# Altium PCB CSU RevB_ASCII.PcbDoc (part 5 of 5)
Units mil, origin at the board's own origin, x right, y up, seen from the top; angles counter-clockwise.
Board outline 5905.51 x 4330.71 mil, 8 copper layers (Top Layer, InternalPlane1, MidLayer1, InternalPlane2, MidLayer2, InternalPlane3, MidLayer3, Bottom Layer); 265 components, 387 nets, 1910 pads, 1151 vias.
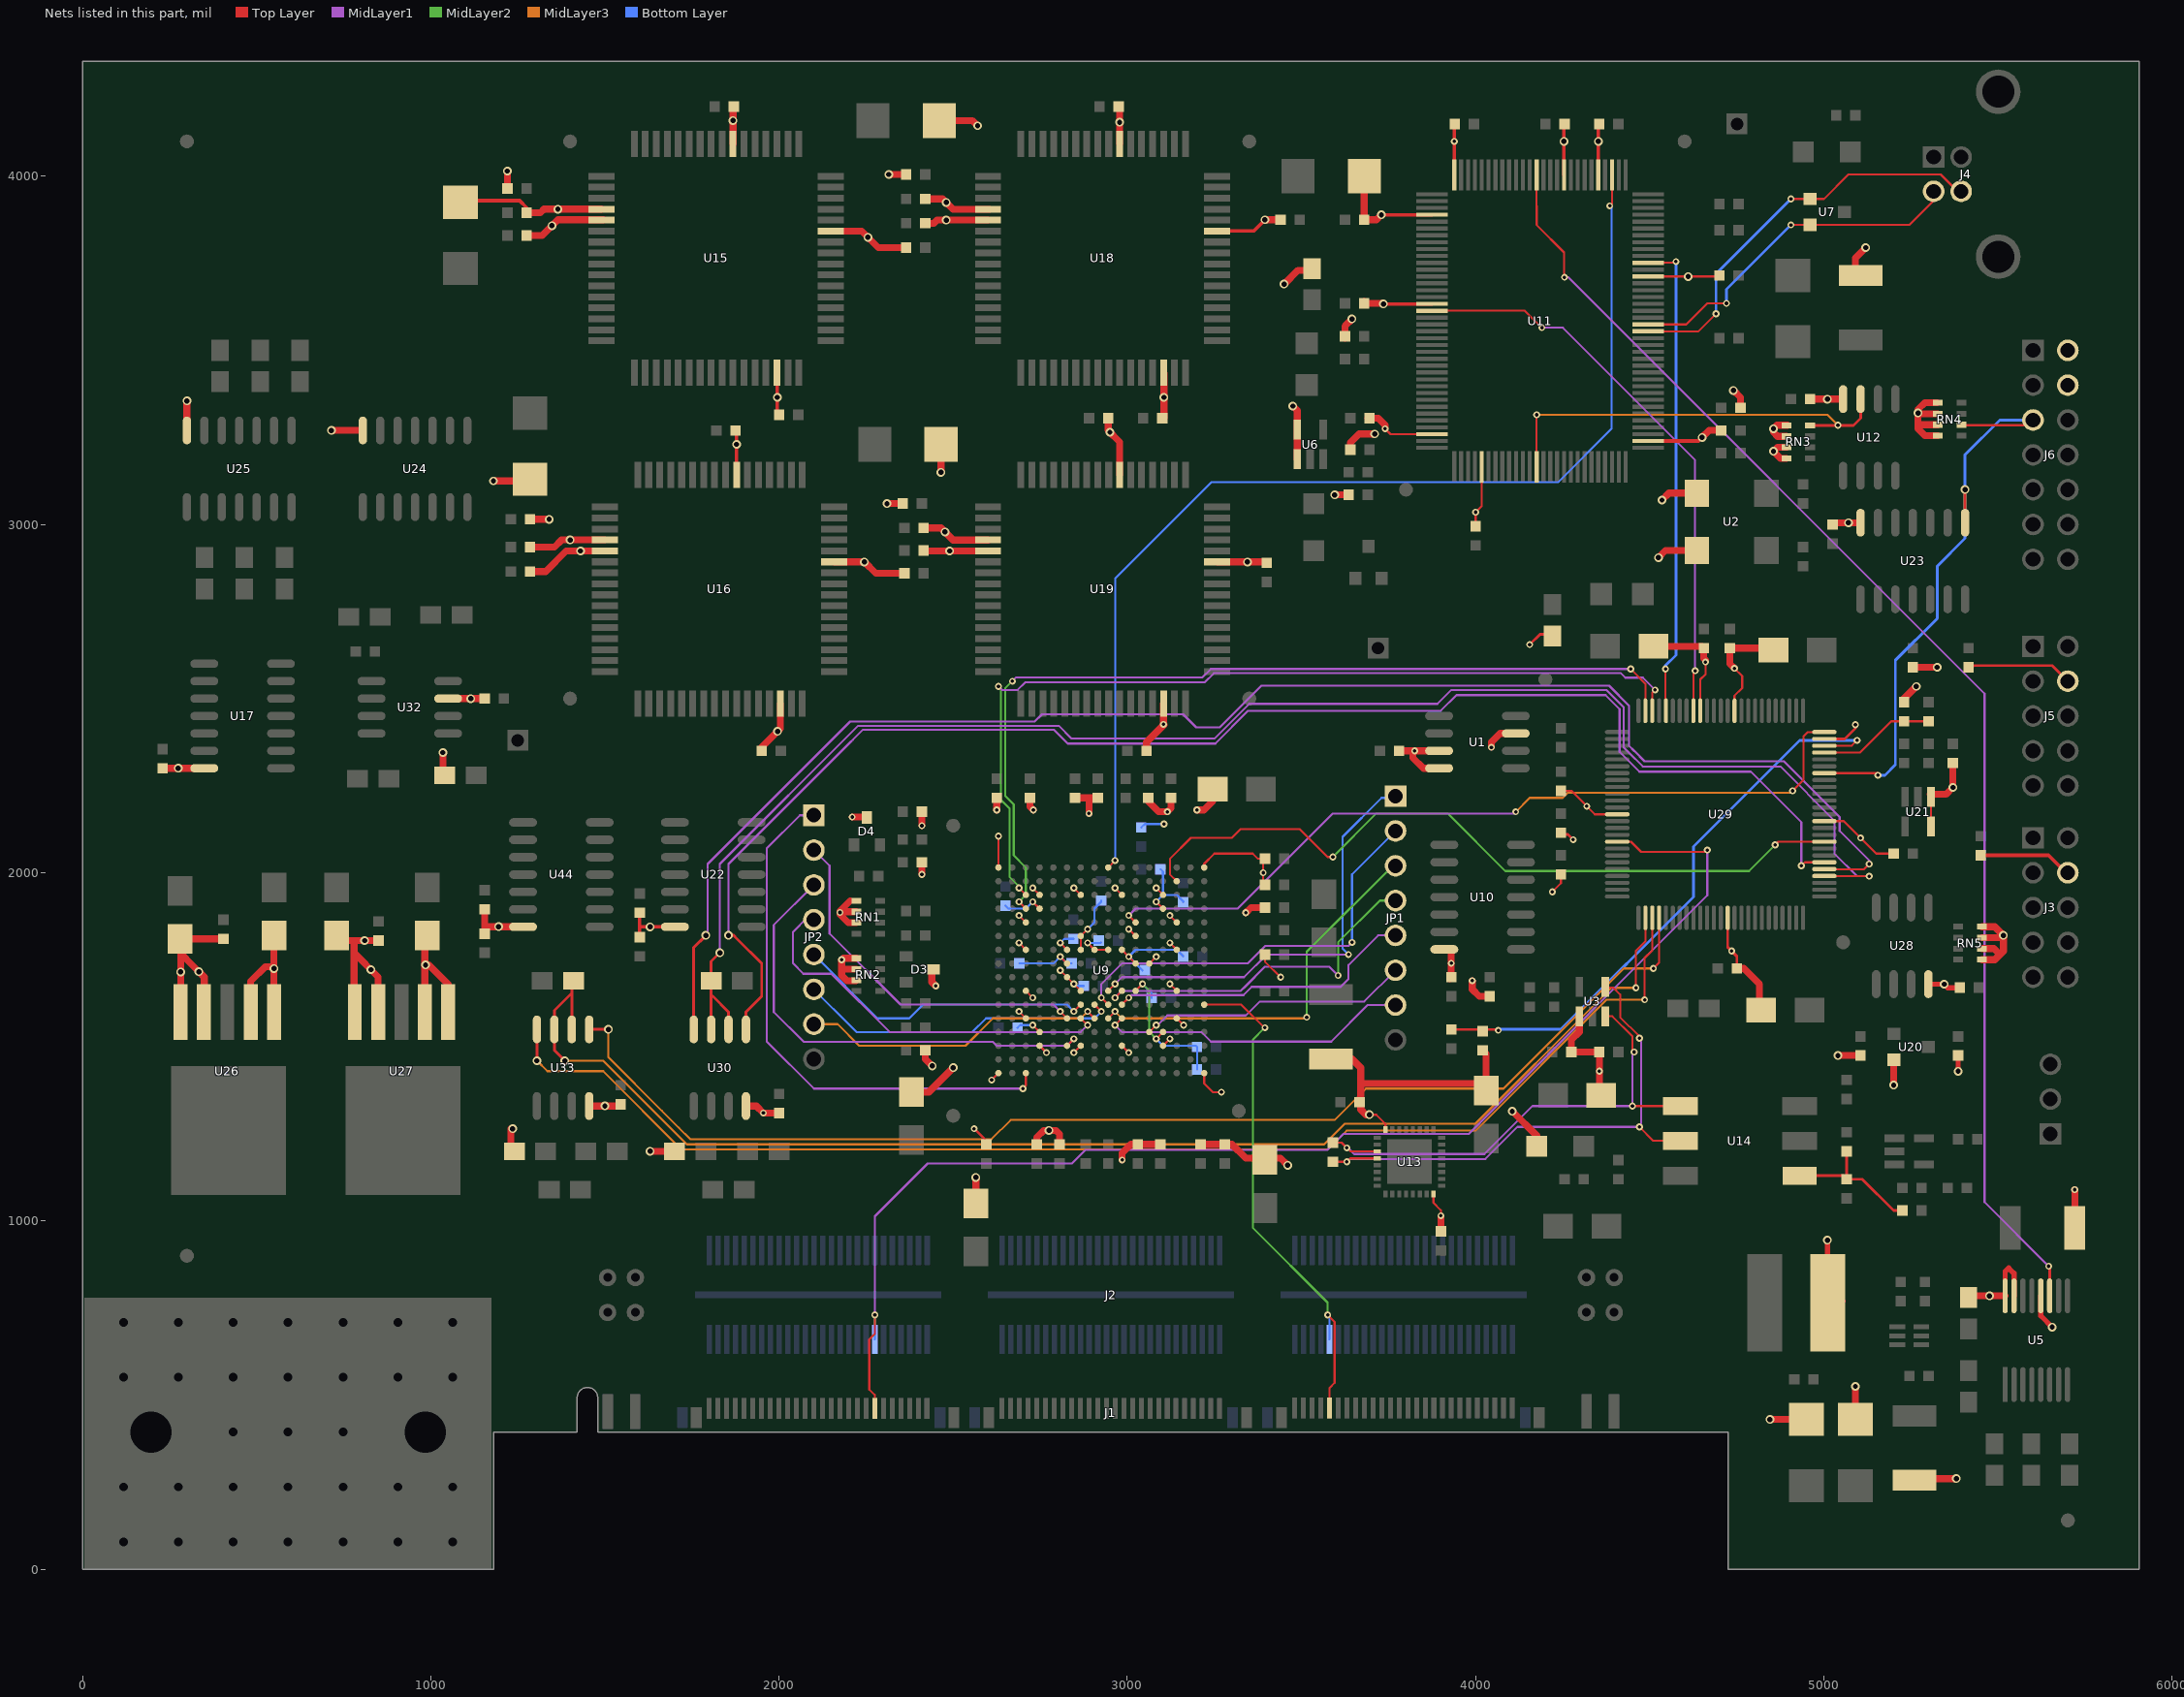
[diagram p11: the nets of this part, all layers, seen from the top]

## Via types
v1: diameter 20, hole 10, Top Layer to Bottom Layer, 647 vias
v2: diameter 25, hole 15, Top Layer to Bottom Layer, 352 vias
v3: diameter 20, hole 10, Top Layer to Bottom Layer, tented top, 151 vias
v4: diameter 20, hole 10, Top Layer to Bottom Layer, tented bottom, 1 vias

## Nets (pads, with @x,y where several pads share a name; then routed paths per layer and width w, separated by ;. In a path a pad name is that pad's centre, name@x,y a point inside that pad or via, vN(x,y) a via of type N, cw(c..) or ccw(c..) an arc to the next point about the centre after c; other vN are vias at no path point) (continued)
TEST_LINE_6: U9.B14 U29.84 | length 2179.4
  Top Layer w6: U9.B14@3141.81,1975.63 3122.13,1995.32 3122.13,2039.57 3182.55,2100 3299.85,2100 3324.85,2125 3495,2125 3575,2045 v1@3595,2045 ; v1(4860,2080) 4869.02,2089.02 U29.84@5001.02,2089.02
  MidLayer2 w6: v1(3590,2045) 3715,2170 3920,2170 4085,2005 4785,2005 v1(4860,2080)
TEST_LINE_7: U9.E11 U29.100 | length 2325.2
  Top Layer w6: v3(3004.02,1877.2) U9.E11@3023.7,1857.52 ; v1(4910,2235) 4941.25,2266.25 4941.25,2391.25 4953.98,2403.98 U29.100@5001.02,2403.98 ; U29.100@5001.02,2405 U29.100@5010,2405
  MidLayer1 w6: v3(3004.02,1877.2) 3023.7,1896.89 3316.89,1896.89 3590,2170 4065,2170 4110,2170 v1(4115,2175)
  MidLayer3 w6: v1(4115,2175) 4155,2215 4250,2215 4265,2230 4905,2230 v1(4910,2235)
TEST_LINE_17: U11.82 U29.17 | length 1655.3
  Top Layer w6: U11.82@3874.45,3613.7 4141.3,3613.7 v1(4190,3565) ; U29.17@4625.04,2465 4625.04,2575.04 v1(4630,2580)
  MidLayer1 w6: v1(4190,3565) 4250.2,3565 4615.37,3199.83 4630,3185.2 v1(4630,2580)
TEST_LINE_21: U11.28 U29.21 | length 1383.9
  Top Layer w6: U11.28@4495,3751.5 4571.5,3751.5 v1(4575,3755) ; U29.21@4545,2465 v1(4545,2585)
  Bottom Layer w8: v1(4545,2585) 4545,2595 4575,2625 v1(4575,3755)
TEST_LINE_23: U9.C3 U29.23 | length 2623.6
  Top Layer w6: v3(2689.06,1955.94) U9.C3@2708.74,1936.26 ; U29.23@4506.93,2465 4506.93,2516.93 v1(4515,2525)
  MidLayer1 w6: v1(2630,2535) 2640,2525 2685,2525 2707,2547 3222,2547 3248,2573 4417,2573 4430,2560 4480,2560 v1(4515,2525)
  MidLayer2 w6: v1(2630,2535) 2637,2528 2637,2209.68 2661.68,2185 2661.68,1988 2689.06,1960.63 v3(2689.06,1955.94)
TEST_LINE_24: U9.D3 U29.24 | length 2629.9
  Top Layer w6: v3(2689.06,1916.57) U9.D3@2708.74,1896.89 ; v1(4445,2585) 4487.24,2542.76 U29.24@4487.24,2465
  MidLayer1 w6: v1(2670,2550) 2681,2561 3215.8,2561 3239.8,2585 v1(4445,2585)
  MidLayer2 w6: v1(2670,2550) 2649,2529 2649,2221 2673.68,2196.32 2673.68,2050.06 2708.74,2015 2708.74,1936.26 v3(2689.06,1916.57)
TG: J1.43 J2.43 U9.L16 | length 1489.5
  Top Layer w6: U9.L16@3220.55,1621.3 3326.73,1621.3 3393.03,1555 v1(3395,1555) ; v1(3575,730) 3595,710 3595,535 3580.21,520.21 J1.43@3580.21,462.85
  MidLayer2 w6: v1(3395,1555) 3360,1520 3360,980.71 3575,765.71 v1(3575,730)
  Bottom Layer w6: v1@3575,735 3580,730 3580,660.35 J2.43@3580.51,659.84
TMS_M: J6.5 RN4.2 U23.8 U29.94 | length 1742.2
  Top Layer w6: U29.94@5001.02,2285.87 5154.13,2285.87 5155,2285 v1(5155,2280)
  Top Layer w8: RN4.2@5390,3285 5585,3285 J6.5@5600,3300 ; U23.8@5405,3005 v2(5405,3100)
  Bottom Layer w8: v1(5155,2280) 5175,2280 5205,2310 5205,2610 5325,2730 5325,2880 5405,2960 5405,3200 5505,3300 J6.5@5600,3300
TST_1: JP2.1 U9.T3 | length 1582
  Top Layer w6: v3(2700,1380) 2708.74,1388.74 U9.T3@2708.74,1424.45
  MidLayer1 w6: JP2.1@2110,2165 2060,2165 1965,2070 1965,1515 2100,1380 v3@2703.66,1380
TST_2: JP2.2 U9.M6 | length 1041.2
  Top Layer w6: v3(2807.17,1601.61) U9.M6@2826.85,1581.93
  MidLayer1 w6: JP2.2@2100,2065 2145,2020 2145,1825 2348.7,1621.3 2787.48,1621.3 v3(2807.17,1601.61)
TST_3: JP2.3 U9.P6 | length 1350.3
  Top Layer w6: U9.P6@2826.85,1503.19 v3(2846.54,1522.87)
  MidLayer1 w6: JP2.3@2100,1965 1985,1850 1985,1600 2070.79,1514.21 2613.98,1514.21 2625,1503.19 2826.85,1503.19 v3(2846.54,1522.87)
TST_4: JP2.4 U9.M7 | length 1132.1
  Top Layer w6: U9.M7@2866.22,1581.93 v3(2885.91,1562.24)
  MidLayer1 w6: JP2.4@2100,1865 2095,1870 2080,1870 2040.32,1830.32 2040.32,1739.68 2070,1710 2150,1710 2317.44,1542.56 2866.22,1542.56 v3(2885.91,1562.24)
TST_5: JP2.5 U9.L7 | length 874.7
  Top Layer w6: v3(2846.54,1601.61) U9.L7@2866.22,1621.3
  Bottom Layer w6: JP2.5@2100,1765 2283.07,1581.93 2374.09,1581.93 2413.46,1621.3 2826.85,1621.3 v3(2846.54,1601.61)
TST_6: JP2.6 U9.L8 | length 921.2
  Top Layer w6: U9.L8@2905.59,1621.3 v3(2925.28,1601.61)
  Bottom Layer w6: JP2.6@2105,1660 2203.51,1561.49 2222.44,1542.56 2555,1542.56 2594.37,1581.93 2905.59,1581.93 v3(2925.28,1601.61)
TST_7: JP2.7 U9.M8 | length 870.1
  Top Layer w6: v3(2885.91,1601.61) U9.M8@2905.59,1581.93
  MidLayer3 w6: JP2.7@2110,1565 2168.19,1565 2230,1503.19 2535.16,1503.19 2613.9,1581.93 2866.22,1581.93 v3(2885.91,1601.61)
TST_11: JP1.1 U9.K9 | length 1278.8
  Top Layer w6: U9.K9@2944.96,1660.67 v3(2964.65,1680.35)
  MidLayer1 w6: v3(2964.65,1680.35) 2984.33,1700.04 3335.04,1700.04 3400,1765 v1(3635,1765)
  Bottom Layer w6: v1(3635,1765) 3617.94,1782.06 3617.94,2102.94 3730,2215 3765,2215 JP1.1@3770,2220
TST_12: JP1.2 U9.L9 | length 1208.3
  Top Layer w6: v3(2925.28,1640.98) U9.L9@2944.96,1621.3
  MidLayer1 w6: v3(2925.28,1640.98) 2925.28,1680.35 2984.33,1739.41 3345.06,1739.41 3395.65,1790 3635,1790 v1(3645,1800)
  Bottom Layer w6: v1(3645,1800) 3645,1995 JP1.2@3770,2120
TST_13: JP1.3 U9.M9 | length 1138.2
  Top Layer w6: U9.M9@2944.96,1581.93 v3(2964.65,1601.61)
  MidLayer2 w6: v1(3515,1585) 3515,1773.03 3770,2028.03 JP1.3@3770,2030
  MidLayer3 w6: v3(2964.65,1601.61) 2984.33,1581.93 3511.93,1581.93 v1(3515,1585)
TST_14: JP1.4 U9.K10 | length 1025.1
  Top Layer w6: v3(2964.65,1640.98) U9.K10@2984.33,1660.67
  MidLayer1 w6: v3(2964.65,1640.98) 2984.33,1660.67 3325.67,1660.67 3338.02,1673.02 3395,1730 3580,1730 v1(3605,1705)
  MidLayer2 w6: v1(3605,1705) 3605,1800 3725,1920 JP1.4@3770,1920
TST_15: JP1.5 U9.L10 | length 891.4
  Top Layer w6: U9.L10@2984.33,1621.3 v3(3004.02,1640.98)
  MidLayer1 w6: v3(3004.02,1640.98) 3011.7,1648.67 3333.47,1648.67 3357.01,1672.21 3612.21,1672.21 3635,1695 3635,1735 3720,1820 JP1.5@3770,1820
TST_16: JP1.6 U9.N12 | length 780.4
  Top Layer w6: U9.N12@3063.07,1542.56 v3(3082.76,1562.24)
  MidLayer1 w6: v3(3082.76,1562.24) 3087.24,1562.24 3115,1590 3340,1590 3380.21,1630.21 3680.21,1630.21 JP1.6@3770,1720
TST_17: JP1.7 U9.M10 | length 896.3
  Top Layer w6: v3(2964.65,1562.24) U9.M10@2984.33,1581.93
  MidLayer1 w6: v3(2964.65,1562.24) 2984.33,1542.56 3212.44,1542.56 3240,1515 3585,1515 3690,1620 JP1.7@3770,1620
TT_SEL_N: J1.117 J2.117 U29.42 | length 3809
  Top Layer w6: J1.117@2274.71,461.79 2274.71,500.5 2259.21,516 2259.21,660 2275,675.79 v1(2275,730) ; U29.42@4406.54,2089.02 4445.98,2089.02 4475,2060 4660,2060 v1(4665,2065)
  MidLayer1 w6: v1(2275,730) 2275,1013.2 2426.8,1165 2841,1165 2880,1204 3574,1204 3602.85,1232.85 3620,1250 3980,1250 4665,1935 v1(4665,2065)
  Bottom Layer w6: v1(2275,730) 2275,660.04 J2.117@2275.2,659.84
TXD_1: U5.11 U11.52 | length 3834.8
  Top Layer w6: 4174.88,3915 U11.52@4174.88,4003.72 ; 4175,3915 4175,3860 4253.67,3781.33 4253.67,3711.33 v1(4255,3710)
  Top Layer w8: v1(5645,870) 5647.95,867.05 U5.11@5647.95,785
  MidLayer1 w6: v1(4255,3710) 4265.2,3710 5461,2514.2 5461,1054 v1(5645,870)
UCA1_T_R: R49.2 U29.52 U33.2 U33.3 | length 3942.1
  Top Layer w6: v1(4460,1669.48) 4460,1775 4487.24,1802.24 U29.52@4487.24,1870.51
  Top Layer w8: v2(1385,1460) 1355,1490 1355,1605 1405,1655 ; U33.2@1405,1550 R49.2@1405,1690
  MidLayer3 w6: v2(1385,1460) 1495,1460 1735,1220 3565,1220 3615.85,1270.85 3624.15,1279.15 3999.15,1279.15 4347.51,1627.51 4389.48,1669.48 v1(4460,1669.48) ; 1537.36,1417.64 1538.1,1416.9
UCA1RXD: U29.54 U33.1 | length 3587.7
  Top Layer w6: v1(4510,1725) 4526.61,1741.61 U29.54@4526.61,1870.51
  Top Layer w8: U33.1@1455,1550 v2(1510,1550)
  MidLayer3 w6: v2(1510,1550) 1510,1470 1663.97,1316.03 1712.67,1267.33 1745,1235 2610,1235 2665,1290 3595,1290 3685,1380 4080,1380 4347.85,1647.85 4425,1725 v1(4510,1725)
UCA1TXD: U29.53 U33.4 | length 3798.3
  Top Layer w6: v1(4485,1635) 4485,1755 4506.93,1776.93 U29.53@4506.93,1870.51
  Top Layer w8: v2(1305,1460) U33.4@1305,1550
  MidLayer3 w6: v2(1305,1460) 1335,1430 1495,1430 1720,1205 3575,1205 3629.43,1259.43 3999.43,1259.43 4375,1635 v1(4485,1635)
UCA3_T_R: R48.2 U29.79 U30.2 U30.3 | length 4614.8
  Top Layer w6: U29.79@5001.02,1990.59 v1@5129.41,1990.59
  Top Layer w8: U30.3@1805,1550 1805,1645 ; v2(1830,1770) 1805,1745 R48.2@1805,1690 1805,1645 ; U30.2@1855,1550 1855,1600 1810,1645 1805,1645
  MidLayer1 w6: v2(1830,1770) 1830,2025 2227,2422 2803,2422 2840,2385 3249.69,2385 3349.69,2485 3519.69,2485 3890,2485 3930,2525 4375,2525 4425,2475 4425,2360 4438.53,2346.47 4480,2305 4875,2305 5030,2150 5030,2055 5095,1990 v1(5130,1990)
UCA3RXD: U29.81 U30.1 | length 4273.4
  Top Layer w6: v1(4935,2020) 4945,2030 U29.81@5000,2030 ; U29.81@5000,2029.96 U29.81@5001.02,2029.96
  Top Layer w8: v2(1855,1820) 1870,1820 1880.25,1809.75 1950,1740 1950,1645 1905,1600 U30.1@1905,1550
  MidLayer1 w6: v2(1855,1820) 1855,2025 2205.52,2375.52 2212.1,2382.1 2240,2410 2790,2410 2829,2371 3252.66,2371 3346.66,2465 3516.66,2465 3900,2465 3945,2510 4373.03,2510 4413,2470.03 4413,2347 4470,2290 4790,2290 4935,2145 v1(4935,2020)
UCA3TXD: U29.80 U30.4 | length 4515.3
  Top Layer w6: U29.80@5000,2010 5115,2010 v1(5130,2025)
  Top Layer w8: U30.4@1755,1550 1755,1785 v2(1790,1820)
  MidLayer1 w6: v2(1790,1820) 1795,1825 1795,2025 2204,2434 2734,2434 2755,2455 3160,2455 3197.72,2417.28 3265,2417.28 3384.72,2537 4383,2537 4440,2480 4440,2365 4455.74,2349.26 ; 4455.42,2349.58 4485,2320 4885,2320 5045,2160 5045,2120 5130,2035 v1(5130,2025)
USBD+: J4.3 U7.1 U11.18 | length 1174
  Top Layer w6: U11.18@4495,3554.65 4639.65,3554.65 v1(4690,3605) ; v1(4905,3935) 5000,3935 5070,4005 5335,4005 5385,3955 5392.01,3955 J4.3@5393.7,3956.69
  Bottom Layer w8: v1(4690,3605) 4690,3720 v1(4905,3935)
USBD-: J4.2 U7.2 U11.19 | length 1017.5
  Top Layer w6: U11.19@4495,3574.33 4604.33,3574.33 4665,3635 v1(4720,3635) ; v1(4905,3860) 4959.8,3860 U7.2@4960,3860.2 5245.2,3860.2 5315,3930 5315,3956.65 J4.2@5314.96,3956.69
  Bottom Layer w8: v1(4720,3635) 4720,3675 v1(4905,3860)
VCC: C1.1 C3.2 C4.1 C8.2 C10.1 C11.1 C12.1 C15.2 C18.2 C20.2 C22.2 C23.1 C25.2 C26.2 C27.2 C28.2 C30.2 C32.1 C39.1 C40.1 C41.1 C42.2 C43.2 C44.2 C45.2 C47.2 C48.2 C49.1 C50.2 C51.2 C52.2 C53.2 C55.1 C56.1 C57.2 C58.2 C59.2 C60.2 C61.2 C62.2 C63.2 C64.2 C65.2 C66.2 C67.2 C68.1 C69.1 C70.1 C71.1 C72.1 C73.2 C75.2 C76.2 C77.1 C78.1 C79.1 C80.1 C81.1 C82.1 C83.1 C84.1 C85.1 C86.1 C87.1 C88.1 C89.1 C90.1 C91.1 C92.1 C93.1 C94.1 C95.1 C96.1 C97.1 C98.1 C99.1 C103.1 C104.1 C107.1 C108.1 C109.1 C111.1 C112.1 C113.2 C137.1 C138.1 C140.2 C142.1 D3.3 D4.3 J3.4 J5.4 J6.2 J6.4 L1.1 L3.1 L4.2 L5.1 L6.2 R1.1 R4.1 R7.2 R10.1 R11.1 R21.2 R25.2 R26.2 R27.1 R28.2 R29.2 R31.2 R32.1 R40.2 R44.2 R50.1 R53.1 R56.2 R57.2 R58.2 RN1.5 RN1.6 RN1.7 RN2.5 RN2.6 RN2.7 RN3.5 RN3.6 RN3.7 RN3.8 RN4.5 RN4.6 RN4.7 RN4.8 RN5.5 RN5.6 RN5.7 RN5.8 U1.3 U1.7 U1.8 U2.1 U2.4 U3.1 U5.12 U5.15 U5.16 U6.1 U6.5 U9.A1 U9.A16 U9.C4 U9.C7 U9.C10 U9.C13 U9.E3 U9.E14 U9.G3 U9.G14 U9.H12 U9.K3 U9.K14 U9.M3 U9.M14 U9.P4 U9.P7 U9.P10 U9.P13 U9.T1 U9.T16 U10.14 U11.2 U11.26 U11.43 U11.48 U11.64 U11.68 U11.81 U11.100 U11.107 U12.8 U15.4 U15.5 U15.30 U15.43 U15.55 U16.4 U16.5 U16.30 U16.43 U16.55 U17.14 U18.4 U18.5 U18.30 U18.43 U18.55 U19.4 U19.5 U19.30 U19.43 U19.55 U20.2 U21.1 U21.5 U22.14 U23.14 U24.14 U25.14 U26.1 U26.2 U27.1 U27.2 U28.8 U29.11 U29.16 U29.38 U29.64 U29.87 U30.8 U32.3 U33.8 U44.14 | length 17426.3
  Top Layer w6: C40.1@1085,3925 C40.1@1090,3930 ; U15.5@1490,3874.01 1490.99,3875 U15.5@1495,3875 ; R53.1@1700,1200 R53.1@1705,1200 ; U15.30@1993.94,3436 U15.30@1995,3434.94 ; v1@2175,1880 v1(2175,1885.98) ; v1@2175,1890 v1@2177.01,1887.99 ; 2180,1720 2182.99,1722.99 ; 2204.49,1919.49 RN1.5@2222,1919.49 ; RN2.5@2216.49,1760 RN2.5@2222,1754.49 ; C58.2@2415,2924.99 C58.2@2415.98,2924.01 ; v3(2610.32,1404.76) U9.T1@2630,1424.45 ; U9.A1@2630,2015 v1(2630,2105) ; v3(2689.06,1601.61) U9.M3@2708.74,1581.93 ; v3(2689.06,1798.46) U9.G3@2708.74,1778.78 ; v3(2689.06,1877.2) U9.E3@2708.74,1857.52 ; U9.K3@2708.74,1660.67 v3(2728.43,1640.98) ; v3(2728.43,1955.94) U9.C4@2748.11,1936.26 ; C96.1@2735,1220 C96.1@2739.99,1224.99 ; U9.P4@2748.11,1503.19 v3(2767.8,1483.5) ; C95.1@2814.99,1220 C95.1@2814.99,1230.01 ; v3(2846.54,1483.5) U9.P7@2866.22,1503.19 ; v3(2846.54,1955.94) U9.C7@2866.22,1936.26 ; v3(2964.65,1955.94) U9.C10@2984.33,1936.26 ; C61.2@2975,4199.99 C61.2@2977.95,4197.04 ; U9.P10@2984.33,1503.19 v3(3004.02,1483.5) ; U9.H12@3063.07,1739.41 v3(3082.76,1759.09) ; v3(3082.76,1955.94) U9.C13@3102.44,1936.26 ; C93.1@3094.99,1220 C93.1@3099.99,1220 ; C66.2@3100,3304.99 C66.2@3105,3309.99 ; U9.P13@3102.44,1503.19 v3(3122.13,1522.87) ; v1@3115,2170 v1(3115,2175) ; v3(3122.13,1680.35) U9.K14@3141.81,1660.67 ; v3(3122.13,1798.46) U9.G14@3141.81,1778.78 ; v3(3122.13,1877.2) U9.E14@3141.81,1857.52 ; U9.M14@3141.81,1581.93 v3(3161.5,1562.24) ; C91.1@3199.99,1220 C91.1@3215,1220 ; U9.T16@3220,1425 U9.T16@3225,1425 ; U9.A16@3220,2015 3220,2025 3250,2055 3360,2055 3375,2040 C87.1@3394.99,2040 ; U9.T16@3220.55,1424.45 3220.55,1394.45 3245,1370 v1(3270,1370) ; U19.43@3255,2895 U19.43@3258,2895 ; C87.1@3390,2030 3390,1967.91 C88.1@3392.6,1965.31 ; C90.1@3395,1764.99 3395,1745 v1(3440,1700) ; C22.2@3685,3309.99 3689.99,3305 C22.2@3695,3305 ; v1(3740,3275) 3755.63,3259.37 U11.100@3874.45,3259.37 ; C25.2@4000.01,2995 v1(4000,3035.2) 4017.4,3052.6 U11.107@4017.4,3165.63 ; U1.3@4115,2400 U1.3@4120,2400 ; v1(4220,1945) 4244.99,1969.99 R58.2@4244.99,1995 ; C79.1@4245.01,2235 4275,2235 v1(4319.04,2190.97) 4320,2190 4342.24,2167.76 U29.38@4406.54,2167.76 ; C30.2@4253.62,4148.62 C30.2@4255,4150 ; C28.2@4350,4150 C28.2@4352.05,4147.95 ; U11.2@4475,3240 U11.2@4495,3240 ; U11.2@4494.68,3240 U11.2@4495,3239.68 ; U2.1@4634.94,2915 U2.1@4635,2915 ; U29.16@4645,2465 4645,2555 4660,2570 v1@4660,2610 ; C27.2@4697.12,3712.13 C27.2@4700,3715.01 ; U29.11@4743.15,2465 4743.15,2508.15 4765,2530 4765,2565 v1(4743.15,2586.85) ; U29.87@5001.02,2148.07 5056.93,2148.07 5150.01,2054.99 C80.1@5200,2054.99 ; R31.2@5250,2590 R31.2@5254.99,2590 ; U21.5@5307.4,2132.68 5307.4,2222.4 U21.1@5310,2225
  Top Layer w8: v1(2560,1265) 2594.99,1230.01 C97.1@2594.99,1220 ; v1(4155,2655) 4185,2685 R29.2@4220,2685 ; R57.2@4245,2110 4265,2110 v1(4280,2095) ; U11.26@4495,3712.13 C27.2@4697.12,3712.13 ; U29.64@4723.46,1870.51 4723.46,1786.54 4730.72,1779.28 4750,1760 C113.2@4750,1724.99 ; C10.1@5415.01,2590 5425,2590 5430,2595 5655,2595 J5.4@5700,2550
  Top Layer w10: C40.1@1090,3930 1255,3930 1275,3910 ; C76.2@1600.01,1815 C75.2@1600.01,1884.98 ; 1600.01,1844.57 U22.14@1701.14,1844.57 ; v2(1630,1844.57) v2@1630,1845 ; C53.2@1875,3269.99 1877.95,3267.04 U16.55@1877.95,3143 ; C47.2@1995,3310 U15.30@1995,3434.94 ; U18.43@3258,3842.52 3362.51,3842.52 v2(3395,3875.01) ; v2(3729.29,3889.29) U11.68@3874.45,3889.29 ; v2@3730,3633.39 U11.81@3874.45,3633.39 ; U11.64@3938.66,4003.72 3938.66,4148.66 C15.2@3940,4150.01 ; U11.48@4253.62,4003.72 C30.2@4253.62,4148.62 ; U11.43@4352.05,4003.72 4352.05,4147.06 C28.2@4355,4150.01 ; U11.2@4495,3239.68 4639.68,3239.68 v2(4650,3250) ; U2.4@4634.94,3090 4635,3090.06 U2.4@4635,3100 ; C12.1@5445,2050 5645,2050 5695,2000 J3.4@5700,2000
  Top Layer w15: L6.2@5010,760 v2(5010,945) ; L6.2@5010,770 L6.2@5055,770 ; U28.8@5300,1680 v2(5345,1680) 5355.01,1669.99 C108.1@5390,1669.99 ; v2(5385,1430) C138.1@5385.01,1475 ; U5.16@5520,785 5520,855 5530,865 5545.59,849.41 U5.15@5545.59,785 ; U5.12@5622.36,785 5622.36,727.64 v2(5655,695)
  Top Layer w20: C49.1@230.01,2300 U17.14@355,2300 ; U25.14@300,3270 v2(300,3355) ; U26.2@483,1600.29 483,1688 525,1730 545,1730 v2(550,1725) ; U26.1@550,1605 C77.1@550,1820 ; v2(715,3270) U24.14@805,3270 ; U27.2@983,1600.29 983,1818 C78.1@985,1820 ; v2@983,1733 v2(985,1735) 995,1735 1050,1680 U27.1@1050,1600.29 ; R44.2@1035,2280 v2(1035,2345) ; U32.3@1055,2500 C140.2@1155,2500.01 ; C63.2@1155.01,1825 C71.1@1155.01,1895 ; 1155.01,1845 U44.14@1264.96,1845 ; v2(1180,3125) C41.1@1285,3125 ; R25.2@1220,3965.01 v2(1220,4015) ; R50.1@1230,1190 v2@1230,1265 ; R50.1@1240,1195 R50.1@1240,1200 ; C44.2@1275.01,3830 1320,3830 v2@1348.27,3858.27 ; C42.2@1275.01,3895 1315,3895 1325.51,3905.51 U15.4@1490,3905.51 ; C45.2@1285.01,2865 1330,2865 1389.01,2924.01 U16.5@1500,2924.01 ; C43.2@1285.01,2935 1355,2935 1375.51,2955.51 U16.4@1500,2955.51 ; R26.2@1285,3014.99 v2@1339.99,3014.99 ; v2(1348.04,3858.04) 1365,3875 U15.5@1495,3875 ; v2@1400,2955 v2(1400,2955.51) ; U33.8@1455,1330 C142.1@1540,1330 ; v2(1630,1200) R53.1@1705,1200 ; U15.55@1867.95,4093 1867.95,4197.94 C52.2@1870,4199.99 ; U30.8@1905,1330 1935,1330 v1(1955,1310) C137.1@2000.01,1310 ; C48.2@1950,2349.99 1950,2360 2003.94,2413.94 U16.30@2003.94,2486 ; U15.43@2148,3842.52 2237.48,3842.52 2285,3795 C50.2@2365,3795.01 ; U16.43@2158,2892.52 v2(2245,2892.52) 2277.52,2860 C51.2@2360,2860.01 ; v1@2175,1880 2198.5,1856.5 RN1.7@2222,1856.5 ; v1@2175,1890 2204.49,1919.49 ; v1@2177.01,1887.99 RN1.6@2222,1887.99 ; 2182.99,1722.99 RN2.6@2222,1722.99 ; v1(2210,2160) D4.3@2255,2160 ; RN2.7@2220,1690 2195,1690 2180,1705 v1(2180,1750) 2184.49,1754.49 RN2.5@2222,1754.49 ; v2(2310,3060) R28.2@2355,3060.01 ; v2@2315.01,4004.99 R27.1@2365,4004.99 ; v1(2410,1995) C98.1@2410,2030.01 ; v1(2410,2135) C103.1@2410,2175.01 ; C60.2@2415.01,2990 2465,2990 2477.71,2977.29 2500,2955 U19.4@2600,2955 ; C58.2@2415.98,2924.01 U19.5@2600,2924.01 ; C99.1@2420,1495 2420,1465 v2(2440,1445) ; C57.2@2420.01,3865 2445,3865 2454.01,3874.01 U18.5@2600,3874.01 ; C59.2@2420.01,3935 2470,3935 2500,3905 U18.4@2605,3905 ; D3.3@2438.74,1722.6 2438.74,1686.26 v1(2450,1675) ; C55.1@2460,4145 2460,4150 2470,4160 2555,4160 v2(2570,4145) ; v2(2465,3150) C56.1@2465,3230 ; C109.1@2565,1055 v2(2565,1125) ; v1(2625,2180) C82.1@2625.01,2215 ; C83.1@2720.01,2215 2720.01,2189.99 v1(2730,2180) ; C96.1@2739.99,1220 2739.99,1239.99 2760,1260 2795,1260 2805,1250 C95.1@2804.99,1220 ; C81.1@2850.01,2215 C84.1@2915.01,2215 ; v1(2890,2170) 2890,2215 ; C67.2@2945,3304.99 2945,3270 2977.95,3237.05 U19.55@2977.95,3143 ; U18.55@2977.95,4093 C61.2@2977.95,4197.04 ; v1(2985,1175) 2985,1195 3010,1220 C93.1@3094.99,1220 ; C62.2@3055,2349.99 3055,2375 3105,2425 v1(3103.94,2426.06) U19.30@3103.94,2486 ; C86.1@3060.01,2215 3060.01,2204.99 3090,2175 v1(3115,2175) 3125.01,2185.01 C85.1@3125.01,2215 ; C66.2@3105,3305 U18.30@3105,3435 ; C91.1@3209.99,1220 3300,1220 3340,1180 3440,1180 v2(3460,1160) ; U19.43@3258,2892.52 3397.49,2892.52 C65.2@3400.01,2890 ; v1(3340,1885) 3355,1900 C89.1@3395,1900 ; v2(3395,3875.01) C64.2@3440,3875.01 ; v2(3450,3690) 3490,3730 R4.1@3530,3730 ; v2(3475,3340) 3487.6,3327.4 U6.1@3487.6,3187.68 ; v2@3595.02,3085 R1.1@3635,3085 ; R7.2@3625,3535 3625,3570 v2(3645,3590) ; R10.1@3640,3215 3640,3235 3665,3260 v2(3710,3260) ; C20.2@3680,3640 C20.2@3680,3634.99 3728.39,3634.99 v2@3730,3633.39 ; C32.1@3680,4030 3680,3875.29 3680.15,3875.14 3715.14,3875.14 v2(3729.29,3889.29) ; C22.2@3690,3305 3720,3305 3740,3285 v1(3740,3275) ; C11.1@3780,2350.01 U1.7@3895,2350 ; v1(3825,2350) 3820,2345 3820,2330 3850,2300 U1.8@3895,2300 ; C23.1@3924.99,1695 C23.1@3929.99,1700 v1(3929.99,1740) U10.14@3930,1780 ; v1(3990,1690) 3990,1665 4010,1645 R21.2@4039.99,1645 ; v1(4045,2360) 4045,2375 4070,2400 U1.3@4115,2400 ; v2(4105,1315) 4175,1245 L5.1@4175,1210 ; U3.1@4297.6,1587.68 4297.6,1542.6 4275,1520 C8.2@4275,1484.99 4354.98,1484.99 C1.1@4354.98,1365.02 ; C70.1@4515,2645 C70.1@4510,2650 4650,2650 C73.2@4654.99,2645 4655,2615 v1@4660,2610 ; v2(4525,2905) 4545,2925 U2.1@4635,2925 ; v2(4535,3070) 4555,3090 U2.4@4634.94,3090 ; v2(4650,3250) 4670,3270 C26.2@4705,3270.01 ; v2(4740,3385) 4760,3365 R11.1@4760,3335.01 ; v1(4743.15,2586.85) 4730.01,2599.99 C72.1@4730.01,2645 4850,2645 4855,2650 C69.1@4855,2655 ; C113.2@4750,1724.99 4770.01,1724.99 4815,1680 4815,1610 C112.1@4820,1605 ; v2(4845,430) 4845.15,430.15 C104.1@4949.78,430.15 ; RN3.8@4892,3190 4875,3190 v2(4855,3210) 4866.5,3221.5 RN3.7@4892,3221.5 ; RN3.6@4892,3252.99 4867.01,3252.99 4855,3265 v2(4855,3275) 4865,3285 RN3.5@4895,3285 ; C39.1@4960,3360.01 U12.8@5055,3360 ; C68.1@5020,3005 U23.14@5105,3005 ; v2(5040,1475) R56.2@5104.99,1475 ; C107.1@5089.78,430.15 5089.78,524.78 v2(5090,525) ; L3.1@5090,3715 5090,3765 v2(5120,3795) ; v2(5200,1390) U20.2@5200,1460 ; R40.2@5230.01,2490 5230.01,2500.01 v2(5265,2535) ; R31.2@5254.99,2590 v2(5325,2590) ; L1.1@5260,260 v2(5380,260) ; 5270,3285 5271.5,3286.5 RN4.7@5327,3286.5 ; v2(5270,3320) 5272.01,3317.99 RN4.6@5327,3317.99 ; U21.1@5305,2225 5350,2225 v2(5370,2245) R32.1@5370,2314.99 ; RN4.5@5325,3350 5290,3350 5270,3330 5270,3275 5290,3255 RN4.8@5327,3255 ; C4.1@5415,780 5420,785 U5.16@5520,785 ; RN5.5@5453,1750 5490,1750 5515,1775 v2(5515,1820) ; RN5.6@5453,1782.01 5487.99,1782.01 5505,1765 ; RN5.7@5453,1813.5 5508.5,1813.5 v2(5515,1820) ; RN5.8@5453,1845 5490,1845 v2(5515,1820) ; v1(5720,1090) 5720.12,1089.88 L4.2@5720.12,979.96
  other v1: 4354.98,1430 4735,1775 3390,2000 5105,2100 4660,2605 3938.66,4100
  other v2: 5475,785 2775,1260 1235,1265 1500,1330 1195,1845 275,2300 1995.67,2405.67 1115,2500 3345,2892.52 1430,2924.01 2490,2924.01 2476.56,2978.44 5070,3005 1340,3015 3595.01,3084.99 1877.95,3230 2950,3265 5010,3360 1995,3365 3105,3365 3735,3633.39 4610,3712.13 2255.22,3824.78 2480,3874.01 1365,3905.51 2480,3925 2315,4005 4253.62,4100 4352.05,4100 2977.95,4155 1867.95,4160
VCC_1.2V: C102.1 C106.2 C114.2 C115.2 C116.2 C117.2 C118.2 C119.2 C120.2 C121.2 C122.2 C123.2 C124.2 C125.2 C126.1 C129.2 C131.2 C133.2 C135.2 C136.1 U9.D4 U9.D13 U9.F7 U9.F11 U9.G6 U9.G7 U9.G8 U9.G9 U9.G10 U9.H6 U9.H11 U9.J6 U9.K7 U9.K11 U9.N4 U9.N13 U27.4 U27.5 U29.99 | length 2768.9
  Top Layer w6: v3(2728.43,1562.24) U9.N4@2748.11,1542.56 ; v3(2728.43,1916.57) U9.D4@2748.11,1896.89 ; v3(2807.17,1719.72) U9.J6@2826.85,1700.04 U9.K7@2866.22,1660.67 ; v3(2807.17,1759.09) U9.H6@2826.85,1739.41 ; v3(2807.17,1798.46) U9.G6@2826.85,1778.78 ; U9.G7@2866.22,1778.78 U9.F7@2866.22,1818.15 v3(2885.91,1837.83) ; v3(2885.91,1798.46) U9.G8@2905.59,1778.78 U9.G9@2944.96,1778.78 ; U9.G10@2984.33,1778.78 U9.H11@3023.7,1739.41 ; v3(3004.02,1837.83) U9.F11@3023.7,1818.15 ; U9.K11@3023.7,1660.67 v3(3043.39,1680.35) ; v3(3082.76,1522.87) U9.N13@3102.44,1542.56 ; v3(3082.76,1916.57) U9.D13@3102.44,1896.89
  Top Layer w8: U29.99@5001.02,2384.29 5059.29,2384.29 5065,2390 5090,2415 v1(5090,2425)
  Top Layer w20: C102.1@735,1805 C106.2@849.99,1805 ; 780,1770 849,1701 U27.4@849,1600.29 U27.4@850,1601.29 ; 780,1805 780,1602.29 U27.5@782,1600.29 ; C126.1@2380,1370 2430,1370 v2(2500,1440) ; v1(3200,2180) 3220,2180 3245,2205 C136.1@3245,2240
  MidLayer2 w6: v3(3043.39,1680.35) 3063.07,1660.67 3063.07,1542.56 v3(3082.76,1522.87)
  Bottom Layer w6: C133.2@2650.01,1905 2658.12,1896.89 2708.74,1896.89 v3(2728.43,1916.57) ; C121.2@2685,1555.01 2692.24,1562.24 v3(2728.43,1562.24) ; C115.2@2690,1740.01 2690.6,1739.41 2787.48,1739.41 v3(2807.17,1759.09) 2826.27,1739.99 C116.2@2840,1739.99 ; v3(2807.17,1798.46) 2818.7,1810 C123.2@2845.01,1810 ; v3(2846.54,1680.35) 2851.9,1674.99 C125.2@2875,1674.99 ; v3(2885.91,1798.46) 2923.47,1798.46 C129.2@2925,1799.99 ; v3(2885.91,1837.83) 2905.59,1857.52 2905.59,1896.89 2925.01,1916.31 C124.2@2925.01,1920 ; C117.2@3039.99,2130 3049.99,2140 v1(3105,2140) ; v3(3043.39,1680.35) 3070,1653.74 C119.2@3070,1639.99 ; C114.2@3043.39,1719.72 v3(3004.02,1759.09) 3023.7,1778.78 3141.81,1778.78 3160,1760.59 C118.2@3160,1759.09 ; v3(3082.76,1522.87) 3102.44,1503.19 3196.8,1503.19 C120.2@3200,1499.99 C122.2@3200,1434.99 ; v3(3082.76,1916.57) 3083.43,1916.57 3083.43,1917.24 3102.44,1936.26 ; C135.2@3095,2010.01 3102.44,2002.57 3102.44,1936.26 ; C131.2@3159.92,1915 C131.2@3160.01,1915 ; C131.2@3161.5,1916.57 3141.81,1936.26 3102.44,1936.26
  other v2: 828.45,1721.55 810,1805
VCC_2.5_TEST: R41.1 R42.2 U29.98 | length 1700.4
  Top Layer w6: R42.2@3932.45,1547.56 R42.2@3930.01,1550 4062.56,1550 v1(4065,1547.56) ; U29.98@5000,2365 5080,2365 v1(5095,2380)
  Bottom Layer w8: v1(4065,1547.56) 4067.44,1550 4245,1550 4625,1930 4625,2075 4930,2380 5075,2380 v1(5095,2380)
VCC_2.5V: C29.1 C33.2 C36.2 C101.1 C105.2 L7.2 R41.2 U13.16 U13.32 U26.4 U26.5 | length 1635.4
  Top Layer w6: U26.5@280,1600 U26.5@280,1600.29 ; v2(3695,1305) 3715,1305 3741.1,1278.9 U13.32@3741.1,1262.52 ; U13.16@3878.9,1077.48 3878.9,1052.32 3900,1031.21 v1@3900,1010 ; C29.1@4025,1400 R41.2@4025,1494.99
  Top Layer w20: v2@280,1715 v2(282,1715) ; U26.5@282,1600.29 C101.1@282,1768 ; U26.4@349,1600.29 350,1601.29 350,1700 316.88,1733.12 C101.1@282,1768 ; C105.2@405,1805 400,1810 C101.1@280,1810 C101.1@282,1808 ; L7.2@3589.84,1460 L7.2@3584.96,1464.88 3645.12,1464.88 3670,1440 3670,1320 3685,1305 v2(3695,1305) ; 3670,1400 3675,1395 C29.1@4030,1395 ; C33.2@3900.01,970 v1@3900.01,1009.99 ; R41.2@4019.99,1490 4030,1479.99 C29.1@4030,1375 ; C101.1@282,1768 C101.1@282,1808 ; C101.1@282,1768 C101.1@282,1808 ; C101.1@282,1768 C101.1@282,1808
  other v1: 3900,1015
  other v2: 334.57,1715.43
VCC_TEST: R39.2 R40.1 U29.97 | length 326.2
  Top Layer w6: U29.97@5001.02,2344.92 5060,2344.92 ; 5060,2345 5103.03,2345 5193.03,2435 R40.1@5220,2435 ; R40.1@5230.01,2435 R39.2@5299.99,2435
VCO_CONTROL: C34.1 C37.2 R59.2 U14.1 | length 416.4
  Top Layer w8: U14.1@4930,1130 5055.01,1130 C37.2@5065.01,1120 ; C34.1@5065.01,1200 C37.2@5065.01,1120 ; R59.2@5225,1030.01 5199.99,1030.01 5110,1120 C37.2@5065.01,1120
VCX_N: R23.1 U3.4 U13.4 U14.5 | length 1605.9
  Top Layer w6: R23.1@3590.01,1170 v1(3630,1170) 3639.84,1179.84 U13.4@3717.48,1179.84 ; U3.4@4375,1672.32 U3.4@4372.4,1672.32 4374.72,1670 4395,1670 4415,1650 4415,1585 4470,1530 v1(4470,1525) ; v1(4470,1270) 4510,1230 U14.5@4585,1230
  MidLayer1 w6: v1(3630,1170) 3638.04,1178.04 4027.97,1178.04 4119.93,1270 v1(4470,1270) 4475,1275 4475,1520 v1(4470,1525)
VCX_P: R23.2 U3.3 U13.3 U14.4 | length 1478.2
  Top Layer w6: R23.2@3590.01,1225 3615,1225 3640.47,1199.53 U13.3@3717.48,1199.53 ; U3.3@4372.4,1587.68 4392.32,1587.68 4450,1530 4450,1490 v1(4455,1485) ; v1(4450,1330) U14.4@4590,1330
  MidLayer1 w6: v1(3630,1210) 3633.04,1210 3651,1192.04 4025,1192.04 4162.96,1330 v1(4450,1330) 4450,1490 v1(4455,1485)
WR_N: U9.A9 U11.41 | length 3174.8
  Top Layer w6: U9.A9@2945,2015 v1@2964.82,2034.82 ; v1(4385,3915) 4391.42,3921.42 U11.41@4391.42,4003.72
  Bottom Layer w6: v1(2964.65,2035) 2965.4,2035.75 2965.4,2845.51 3241,3121.11 4236.11,3121.11 4390,3275 4390,3910 v1(4385,3915)
WRPROTECT: RN3.4 U11.115 U12.7 | length 1235.2
  Top Layer w6: U11.115@4174.88,3165.63 v1@4174.88,3314.88
  Top Layer w8: RN3.4@4960.01,3284.49 5084.49,3284.49 5105,3305 U12.7@5105,3360
  MidLayer3 w6: v1(4175,3315) 5010,3315 v1(5040,3285)
pads on no net: 1. 2. ?. D1.2 J1.120 J2.120 J4.1 J5.6 J5.7 J5.8 J6.6 J6.10 J6.13 U5.1 U5.10 U9.B3 U9.B10 U9.B12 U9.C9 U9.D9 U9.D12 U9.E9 U9.F16 U9.J15 U9.L14 U9.L15 U11.6 U11.7 U11.8 U11.9 U11.11 U11.14 U11.15 U11.16 U11.21 U11.22 U11.23 U11.29 U11.30 U11.31 U11.34 U11.38 U11.39 U11.42 U11.50 U11.51 U11.66 U11.67 U11.69 U11.71 U11.84 U11.98 U11.126 U11.127 U11.128 U13.5 U13.6 U13.7 U15.36 U15.37 U15.38 U15.40 U15.41 U15.42 U15.44 U15.45 U15.47 U15.48 U15.54 U15.56 U16.36 U16.37 U16.38 U16.40 U16.41 U16.42 U16.44 U16.45 U16.47 U16.48 U16.54 U16.56 U18.36 U18.37 U18.38 U18.40 U18.41 U18.42 U18.44 U18.45 U18.47 U18.48 U18.56 U18.57 U19.36 U19.37 U19.38 U19.40 U19.41 U19.42 U19.44 U19.45 U19.47 U19.48 U19.56 U19.57 U29.90 U44.5 U44.6 U44.10 U44.11 U44.12 U44.13

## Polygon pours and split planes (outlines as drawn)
GND on Top Layer "Top Layer-No Net" (solid, remove dead copper, pour order 1000): 100,1500 100,1000 650,1000 650,1500
GND on Top Layer "Top Layer-No Net" (solid, remove dead copper, pour order 1001): 700,1000 1170,1000 1170,1500 700,1500
GND on InternalPlane1 (split plane): 5885.41,20.1 4744.51,20.1 4744.51,393.7 4744.12,397.62 4742.98,401.39 4741.12,404.87 4738.62,407.91 4735.57,410.41 4732.1,412.27 4728.33,413.41 4724.41,413.8 1499.6,413.8 1499.6,492.13 1499.56,492.57 1499.27,497.68 1498.34,503.16 1496.8,508.51 1494.67,513.65 1491.98,518.52 1488.76,523.05 1485.06,527.2 1480.91,530.91 1476.37,534.13 1471.5,536.82 1466.36,538.95 1461.02,540.49 1455.53,541.42 1449.98,541.73 1444.42,541.42 1438.94,540.49 1433.59,538.95 1428.45,536.82 1423.59,534.13 1419.05,530.91 1414.9,527.2 1411.19,523.05 1407.98,518.52 1405.28,513.65 1403.16,508.51 1401.62,503.16 1400.68,497.68 1400.4,492.57 1400.35,492.13 1400.35,413.8 1181.1,413.8 1177.18,413.41 1173.41,412.27 1169.94,410.41 1166.89,407.91 1164.39,404.87 1162.54,401.39 1161.39,397.62 1161.01,393.7 1161.01,20.1 20.1,20.1 20.1,4310.61 5885.41,4310.61
VCC on InternalPlane2 (split plane): 5885.41,20.1 4744.51,20.1 4744.51,393.7 4744.12,397.62 4742.98,401.39 4741.12,404.87 4738.62,407.91 4735.57,410.41 4732.1,412.27 4728.33,413.41 4724.41,413.8 1499.6,413.8 1499.6,492.13 1499.56,492.57 1499.27,497.68 1498.34,503.16 1496.8,508.51 1494.67,513.65 1491.98,518.52 1488.76,523.05 1485.06,527.2 1480.91,530.91 1476.37,534.13 1471.5,536.82 1466.36,538.95 1461.02,540.49 1455.53,541.42 1449.98,541.73 1444.42,541.42 1438.94,540.49 1433.59,538.95 1428.45,536.82 1423.59,534.13 1419.05,530.91 1414.9,527.2 1411.19,523.05 1407.98,518.52 1405.28,513.65 1403.16,508.51 1401.62,503.16 1400.68,497.68 1400.4,492.57 1400.35,492.13 1400.35,413.8 1181.1,413.8 1177.18,413.41 1173.41,412.27 1169.94,410.41 1166.89,407.91 1164.39,404.87 1162.54,401.39 1161.39,397.62 1161.01,393.7 1161.01,20.1 20.1,20.1 20.1,4310.61 5885.41,4310.61
VCC_1.2V on InternalPlane3 (split plane): 5885.41,20.1 4744.51,20.1 4744.51,393.7 4744.12,397.62 4742.98,401.39 4741.12,404.87 4738.62,407.91 4735.57,410.41 4732.1,412.27 4728.33,413.41 4724.41,413.8 4265.09,413.8 4265.09,1495 4264.74,1497.61 4263.74,1500.04 4262.13,1502.13 4260.04,1503.73 4257.61,1504.74 4255,1505.09 3440,1505.09 3437.39,1504.74 3434.96,1503.73 3432.87,1502.13 3431.26,1500.04 3430.26,1497.61 3429.91,1495 3429.91,965.09 610.09,965.09 610.09,1895 609.74,1897.61 608.74,1900.04 607.13,1902.13 605.04,1903.73 602.61,1904.74 600,1905.09 20.1,1905.09 20.1,4310.61 5885.41,4310.61
VCC_2.5V on InternalPlane3 (split plane): 589.91,955 590.26,952.39 591.26,949.96 592.87,947.87 594.96,946.26 597.39,945.26 600,944.91 3440,944.91 3442.61,945.26 3445.04,946.26 3447.13,947.87 3448.74,949.96 3449.74,952.39 3450.09,955 3450.09,1484.91 4244.91,1484.91 4244.91,413.8 1499.6,413.8 1499.6,492.13 1499.56,492.57 1499.27,497.68 1498.34,503.16 1496.8,508.51 1494.67,513.65 1491.98,518.52 1488.76,523.05 1485.06,527.2 1480.91,530.91 1476.37,534.13 1471.5,536.82 1466.36,538.95 1461.02,540.49 1455.53,541.42 1449.98,541.73 1444.42,541.42 1438.94,540.49 1433.59,538.95 1428.45,536.82 1423.59,534.13 1419.05,530.91 1414.9,527.2 1411.19,523.05 1407.98,518.52 1405.28,513.65 1403.16,508.51 1401.62,503.16 1400.68,497.68 1400.4,492.57 1400.35,492.13 1400.35,413.8 1181.1,413.8 1177.18,413.41 1173.41,412.27 1169.94,410.41 1166.89,407.91 1164.39,404.87 1162.54,401.39 1161.39,397.62 1161.01,393.7 1161.01,20.1 20.1,20.1 20.1,1884.91 589.91,1884.91

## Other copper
Bottom Layer:
  text "CSU REV:B" at 1175,4140 h80
InternalPlane1 (plane layer: these items are gaps in the copper):
  the board outline again, w40
InternalPlane2 (plane layer: these items are gaps in the copper):
  lines w20: 4190,398.7 4195,393.7
  lines w40: 0,0 1181.1,0 1181.1,393.7 1420.45,393.7 1420.45,492.13 cw(c1449.98,492.13) 1479.51,492.13 1479.51,394.51 1480.31,393.7 4724.41,393.7 4724.41,0 5905.51,0 5905.51,4330.71 0,4330.71 0,0
InternalPlane3 (plane layer: these items are gaps in the copper):
  lines w20: 0,1895 600,1895 600,955 3440,955 3440,1495 4255,1495 4255,393.7
  lines w40: 0,0 1181.1,0 1181.1,393.7 1420.45,393.7 1420.45,492.13 cw(c1449.98,492.13) 1479.51,492.13 1479.51,394.51 1480.31,393.7 4724.41,393.7 4724.41,0 5905.51,0 5905.51,4330.71 0,4330.71 0,0

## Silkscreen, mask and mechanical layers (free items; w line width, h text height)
Top Overlay:
  region: 750,4000 400,4000 400,3800 750,3800
  text "CSU Board" at 480,4140 h80
  text "REV" at 105,3830 h80
Mechanical 1:
  lines w10: 1180,394 1180,0 0,0 0,4330 5905,4330 5905,0 4725,0 4725,394
Mechanical 2:
  drawing of 240 lines, arcs and shapes, not listed
  text "NOTES:" at 9319.93,7369.82 h100
  text "1. MATERIAL: .062+/- .006 (FINISHED) GLASS EPOXY LAMINATE," at 9330.93,7166.82 h75
  text "TYPE: NEMA GRADE FR4 OR EQUIV." at 10250.93,7006.82 h75
  text "TG 170 MATERIAL OR BETTER." at 10240,6880 h75
  text "1.0 oz COPPER CLAD ON OUTER LAYERS." at 10245,6755 h75
  text "1.0 oz COPPER CLAD ON INNER LAYERS." at 10240,6620 h75
  text "CONSTRUCTION SHALL MEET CLASS 94V-1." at 10230,6485 h75
  text "8  LAYERS." at 10240,6350 h75
  text "2. CONSTRUCTION: LIQUID PHOTO-IMAGEABLE SOLDERMASK OVER BASE COPPER" at 9315.93,6171.82 h75
  text "PER IPC-SM-840B, TYPE B, CLASS 3." at 10560.93,6021.82 h75
  text "COLOR GREEN" at 10565,5905 h75
  text "TOLERANCE: .xxx = .005, .xx = .01" at 10555,5760 h75
  text "LAYER CONSTRUCTION ALIGNMENT MAX: +/-.005" at 10565,5635 h75
  text "3. FINISH: COPPER PLATE-THRU ALL MARKED HOLES." at 9310.93,5496.82 h75
  text "MIN PLATING THICKNESS: 1oz" at 10085.93,5346.82 h75
  text "ALL EXPOSED COPPER PADS & VIAS SHALL BE 3-5 MICRO INCHES" at 10084.93,5212.82 h75
  text "IMMERSION GOLD OR SILVER OVER 150 MICRO INCHES NICKEL (MIN)." at 10079.93,5077.82 h75
  text "5.905" at 5925,4830 h70 r90
  text "SILKSCREEN COMPONENT SIDES(TOP,BOTTOM) ." at 10075.93,4640.82 h75
  text "TYPE: CAT-L-INK OR EQUIV. COLOR: WHITE." at 10080.93,4500.82 h75
  text "SLIKSCREEN TO REMAIN CLEAR OF EXPOSED PADS." at 10075.93,4355.82 h75
  text "4.330" at 6400,4305 h70
  text "REGISTER TOLERANCE: +/-.015" at 10080.93,4205.82 h75
  text "ALL HOLES SHALL BE DRILLED +/- .003 INCH WITH" at 10070.93,2985.82 h75
  text "RESPECT TO CENTER OF DRILLED PAD." at 10042.93,2807.82 h75
  text "ALL HOLES ARE FINISHED SIZE AFTER PLATING." at 10080.93,2670.82 h75
  text "COMPONENT SIDE (.GTL)" at 11865,1905 h50
  text "LAYER CONSTRUCTION DETAIL" at 10114.93,1887.82 h60
  text "GROUND PLANE (.GP1)" at 11990,1795 h50
  text "MID LAYER 1 (.G1)" at 12294.93,1706.82 h50
  text "VOLTAGE PLANE (.GP2)" at 12720.93,1613.82 h50
  text "MID LAYER 2  (.G2)" at 13145,1505 h50
  text "INSULATION" at 9750.93,1499.82 h50
  text "VOLTAGE PLANE (.GP3)" at 12355,1325 h50
  text "MID LAYER 3 (.G3)" at 12020,1225 h50
  text "BOTTOM SIDE (.GBL)" at 11830,1115 h50
  text "HOLE TOLERENCE" at 9731.93,620.82 h60
  text "TOOL" at 10566.93,620.82 h60
  text "HOLE SIZE" at 11006.93,620.82 h60
  text "HOLE COUNT" at 11786.93,620.82 h60
  text "PLATE-THRU" at 13726.93,620.82 h60
  text "SYMBOL" at 12475.93,606.82 h60
  text "NOTE" at 13271.93,600.82 h60
  text "+/-.003" at 9886.93,500.82 h60
  text "0.493" at -1030,495 h70
  text "T1" at 10596.93,490.82 h60
  text "YES" at 13902.93,490.82 h60
  text "799" at 11967.93,487.82 h60
  text "B" at 12580,485 h60
  text "10 MIL" at 11015,480 h60
  text "FINISHED SIZE" at 13032.93,467.82 h60
  text "0.394" at -985,380 h60
  text "15 MIL" at 11026.57,371.97 h60
  text "+/-.003" at 9886.93,370.82 h60
  text "T2" at 10596.93,370.82 h60
  text "A" at 12565,370 h60
  text "352" at 11960,365 h60
  text "YES" at 13902.93,360.82 h60
  text "FINISHED SIZE" at 13032.93,337.82 h60
  text "+/-.003" at 9886.93,250.82 h60
  text "T3" at 10596.93,250.82 h60
  text "C" at 12570,245 h60
  text "25 MIL" at 11026.93,243.82 h60
  text "YES" at 13902.93,240.82 h60
  text "39" at 11976.93,238.82 h60
  text "FINISHED SIZE" at 13032.93,217.82 h60
  text "+/-.003" at 9886.93,130.82 h60
  text "T4" at 10596.93,130.82 h60
  text "E" at 12580,130 h60
  text "YES" at 13902.93,125.82 h60
  text "3" at 11970,120 h60
  text "36 MIL" at 11017.93,112.82 h60
  text "FINISHED SIZE" at 13032.93,97.82 h60
  text "R 0.030" at 2020,45 h70
  text "+/-.003" at 9886.93,10.82 h60
  text "57" at 11970,10 h60
  text "YES" at 13911.93,8.82 h60
  text "D" at 12580,5 h60
  text "42 MIL" at 11020,0 h60
  text "T5" at 10607.93,-4.18 h60
  text "FINISHED SIZE" at 13032.93,-14.18 h60
  text "0.000" at -850,-40 h70
  text "T6" at 10607.93,-104.18 h60
  text "2" at 11990,-110 h60
  text "92 MIL" at 11017.93,-117.18 h60
  text "+/-.003" at 9886.93,-119.18 h60
  text "YES" at 13910,-120 h60
  text "G" at 12570,-125 h60
  text "FINISHED SIZE" at 13031.93,-131.18 h60
  text "T7" at 10617.93,-224.18 h60
  text "2" at 11982.93,-232.18 h60
  text "YES" at 13900,-235 h60
  text "+/-.003" at 9866.93,-239.18 h60
  text "118 MIL" at 10980,-240 h60
  text "F" at 12590,-245 h60
  text "FINISHED SIZE" at 13031.93,-261.18 h60
  text "T8" at 10617.93,-344.18 h60
  text "+/-.003" at 9866.93,-349.18 h60
  text "- MIL" at 10960.63,-351.46 h60
  text "-" at 12541.93,-361.18 h60
  text "-" at 12001.93,-365.18 h60
  text "FINISHED SIZE" at 13031.93,-381.18 h60
  text "T9" at 10617.93,-464.18 h60
  text "+/-.003" at 9866.93,-469.18 h60
  text "- MIL" at 10958.66,-476.46 h60
  text "-" at 11977.93,-482.18 h60
  text "NO" at 13910,-485 h60
  text "FINISHED SIZE" at 13032.93,-504.18 h60
  text "T10" at 10617.93,-584.18 h60
  text "- MIL" at 10962.93,-587.18 h60
  text "+/-.003" at 9846.93,-589.18 h60
  text "YES" at 13891.93,-591.18 h60
  text "-" at 11977.93,-597.18 h60
  text "-" at 12531.93,-606.18 h60
  text "FINISHED SIZE" at 13032.93,-624.18 h60
  text "T11" at 10627.93,-714.18 h60
  text "- MIL" at 10952.93,-717.18 h60
  text "-" at 11952.93,-717.18 h60
  text "+/-.003" at 9866.93,-719.18 h60
  text "YES" at 13891.93,-721.18 h60
  text "FINISHED SIZE" at 13032.93,-754.18 h60
  text "4.725" at 4760,-810 h70 r90
  text "0.000" at 35,-815 h70 r90
  text "1.180" at 1215,-820 h70 r90
  text "1.420" at 1380,-825 h70 r90
  text "T12" at 10617.93,-824.18 h60
  text "-" at 11962.93,-827.18 h60
  text "+/-.003" at 9846.93,-829.18 h60
  text "- MIL" at 10956.93,-831.18 h60
  text "YES" at 13892.93,-837.18 h60
  text "1.480" at 1570,-850 h70 r90
  text "FINISHED SIZE" at 13032.93,-864.18 h60
  text "T13" at 10627.93,-954.18 h60
  text "- MIL" at 10962.93,-957.18 h60
  text "+/-.003" at 9866.93,-959.18 h60
  text "-" at 11977.93,-967.18 h60
  text "NO" at 13910,-980 h60
  text "FINISHED SIZE" at 13032.93,-994.18 h60
  text "NO" at 13921.93,-1086.18 h60
  text "T14" at 10627.93,-1144.18 h60
  text "- MIL" at 10962.93,-1147.18 h60
  text "+/-.003" at 9866.93,-1149.18 h60
  text "-" at 11977.93,-1157.18 h60
  text "FINISHED SIZE" at 13032.93,-1184.18 h60
  text "1.450" at 1490,-1235 h70 r90
  text "TOTALS:" at 10606.93,-1349.18 h60
  text "1254" at 11107.93,-1354.18 h60
  text "Las Cumbres Observatory, Inc" at 10240,-2050 h150
  text "FABRICATION DRAWING" at 10879.93,-2662.18 h150
  text "CSU BOARD" at 11052.93,-2967.18 h120
  text "DATE" at 9654.93,-3365.18 h100
  text "11/09/11" at 10254.93,-3365.18 h100
  text "SIZE" at 11679.93,-3365.18 h100
  text "DRAWING NUMBER" at 12179.93,-3365.18 h100
  text "REV" at 14654.93,-3365.18 h100
  text "SCALE" at 9654.93,-3615.18 h100
  text "2/1" at 10279.93,-3615.18 h100
  text "B" at 14679.93,-3615.18 h150
  text "D" at 11785.93,-3620.18 h150
  text "FAB-CSU" at 12295,-3625 h150
Mechanical 3:
  circle w12: c196.85,393.7 r116.99
  circle w12: c984.25,393.7 r114.78
  lines w3: 9584.93,-3715.18 9584.93,-1715.18 15084.93,-1715.18 ; 9584.93,-3215.18 15084.93,-3215.18 ; 9584.93,-2315.18 15084.93,-2315.18 ; 11584.93,-3715.18 11584.93,-3215.18 ; 12084.93,-3715.18 12084.93,-3215.18 ; 14534.93,-3715.18 14534.93,-3215.18 ; 15084.93,-3712.18 15084.93,7807.82 -4537.07,7807.82 -4537.07,-3712.18 15087.93,-3712.18
  text "Las Cumbres Observatory, Inc" at 10240,-2050 h150
  text "ASSEMBLY  DRAWING" at 10884.93,-2662.18 h150
  text "CSU BOARD" at 11057.93,-2967.18 h120
  text "DATE" at 9659.93,-3365.18 h100
  text "11/09/11" at 10259.93,-3365.18 h100
  text "SIZE" at 11684.93,-3365.18 h100
  text "DRAWING NUMBER" at 12184.93,-3365.18 h100
  text "REV" at 14659.93,-3365.18 h100
  text "SCALE" at 9659.93,-3615.18 h100
  text "2/1" at 10284.93,-3615.18 h100
  text "B" at 14684.93,-3615.18 h150
  text "ASSY-CSU" at 12295,-3620 h150
  text "D" at 11790.93,-3620.18 h150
